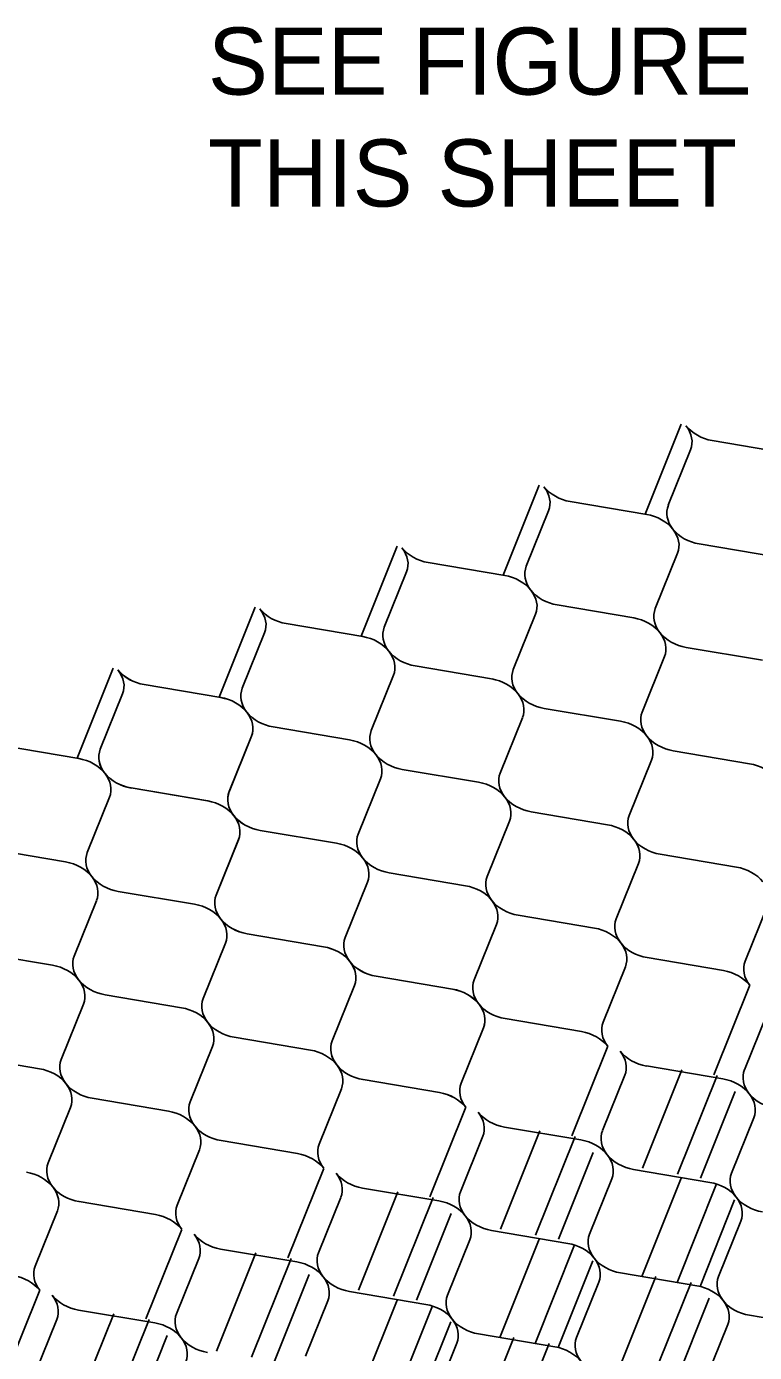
# Model space of a CAD drawing. Extents: x 638850 to 644908, y 297188 to 298900.
# Drawn here: x 639030.2 to 639062.7, y 298337.4 to 298396.7 of the extents above; entities that cross this region are included whole.
import ezdxf

# ---------------------------------------------------------------- set-up
doc = ezdxf.new("R2010")
doc.units = 0
doc.layers.add('1', color=7, linetype='Continuous')
doc.layers.add('2', color=7, linetype='Continuous')

msp = doc.modelspace()

# ---------------------------------------------------------------- linework, layer by layer
at = {"layer": '2'}
for p, q in [((639059.434, 298378.905), (639057.823, 298374.882)), ((639060.816, 298378.176), (639064.234, 298377.598)), ((639058.857, 298375.286), (639059.85, 298377.76)), ((639053.09, 298376.177), (639051.48, 298372.154)), ((639054.472, 298375.448), (639057.891, 298374.87)), ((639052.513, 298372.558), (639053.506, 298375.033)), ((639046.747, 298373.45), (639045.137, 298369.427)), ((639063.653, 298372.974), (639060.236, 298373.554)), ((639059.269, 298373.136), (639058.276, 298370.662)), ((639046.17, 298369.831), (639047.163, 298372.305)), ((639048.129, 298372.721), (639051.547, 298372.143)), ((639040.403, 298370.723), (639038.793, 298366.699)), ((639057.31, 298370.246), (639053.892, 298370.826)), ((639041.785, 298369.993), (639045.204, 298369.415)), ((639052.925, 298370.409), (639051.933, 298367.934)), ((639039.827, 298367.103), (639040.819, 298369.578)), ((639059.651, 298368.93), (639063.07, 298368.352)), ((639050.966, 298367.519), (639047.549, 298368.099)), ((639057.692, 298366.04), (639058.685, 298368.515)), ((639034.061, 298367.997), (639032.451, 298363.974)), ((639046.582, 298367.681), (639045.589, 298365.207)), ((639035.442, 298367.266), (639038.861, 298366.688)), ((639035.443, 298367.268), (639038.861, 298366.69)), ((639033.483, 298364.376), (639034.476, 298366.85)), ((639033.484, 298364.378), (639034.477, 298366.853)), ((639051.349, 298363.313), (639052.342, 298365.787)), ((639053.308, 298366.203), (639056.726, 298365.625)), ((639044.623, 298364.791), (639041.205, 298365.371)), ((639029.1, 298364.541), (639032.518, 298363.962)), ((639040.239, 298364.954), (639039.246, 298362.479)), ((639040.239, 298364.956), (639039.247, 298362.481)), ((639062.489, 298363.728), (639059.071, 298364.308)), ((639046.964, 298363.475), (639050.383, 298362.897)), ((639058.104, 298363.89), (639057.111, 298361.416)), ((639045.006, 298360.585), (639045.998, 298363.06)), ((639033.896, 298362.228), (639032.903, 298359.754)), ((639038.28, 298362.064), (639034.862, 298362.644)), ((639038.281, 298362.066), (639034.863, 298362.646)), ((639056.145, 298361), (639052.728, 298361.581)), ((639051.761, 298361.163), (639050.768, 298358.688)), ((639040.621, 298360.748), (639044.039, 298360.17)), ((639040.622, 298360.75), (639044.04, 298360.172)), ((639031.937, 298359.338), (639028.52, 298359.918)), ((639038.662, 298357.858), (639039.655, 298360.332)), ((639038.663, 298357.86), (639039.656, 298360.334)), ((639056.528, 298356.795), (639057.521, 298359.269)), ((639058.487, 298359.685), (639061.905, 298359.106)), ((639049.802, 298358.273), (639046.384, 298358.853)), ((639034.278, 298358.022), (639037.697, 298357.444)), ((639045.417, 298358.435), (639044.425, 298355.961)), ((639045.418, 298358.438), (639044.426, 298355.963)), ((639032.32, 298355.132), (639033.312, 298357.607)), ((639052.143, 298356.957), (639055.562, 298356.379)), ((639063.283, 298357.372), (639062.29, 298354.898)), ((639050.184, 298354.067), (639051.177, 298356.542)), ((639039.075, 298355.71), (639038.082, 298353.236)), ((639043.459, 298355.545), (639040.041, 298356.126)), ((639043.459, 298355.548), (639040.042, 298356.128)), ((639027.935, 298355.295), (639031.354, 298354.717)), ((639061.324, 298354.482), (639057.907, 298355.062)), ((639056.94, 298354.645), (639055.947, 298352.17)), ((639045.8, 298354.23), (639049.218, 298353.652)), ((639045.801, 298354.232), (639049.219, 298353.654)), ((639037.116, 298352.82), (639033.698, 298353.4)), ((639043.841, 298351.34), (639044.834, 298353.814)), ((639043.842, 298351.342), (639044.835, 298353.816)), ((639062.495, 298353.825), (639060.895, 298349.827)), ((639032.732, 298352.983), (639031.739, 298350.508)), ((639054.981, 298351.755), (639051.563, 298352.335)), ((639062.264, 298350.052), (639063.257, 298352.526)), ((639039.457, 298351.504), (639042.876, 298350.926)), ((639050.597, 298351.919), (639049.604, 298349.445)), ((639050.596, 298351.917), (639049.604, 298349.443)), ((639037.498, 298348.614), (639038.491, 298351.089)), ((639056.152, 298351.097), (639054.552, 298347.101)), ((639030.773, 298350.093), (639027.355, 298350.673)), ((639055.921, 298347.327), (639056.914, 298349.801)), ((639059.458, 298350.052), (639057.698, 298345.654)), ((639057.88, 298350.217), (639061.298, 298349.636)), ((639061.035, 298349.788), (639059.273, 298345.388)), ((639044.254, 298349.192), (639043.261, 298346.717)), ((639048.638, 298349.027), (639045.22, 298349.607)), ((639048.638, 298349.029), (639045.221, 298349.61)), ((639033.114, 298348.777), (639036.532, 298348.199)), ((639061.848, 298349.078), (639060.3, 298345.209)), ((639031.155, 298345.887), (639032.148, 298348.361)), ((639049.808, 298348.37), (639048.209, 298344.374)), ((639053.115, 298347.325), (639051.355, 298342.927)), ((639051.537, 298347.489), (639054.955, 298346.911)), ((639062.675, 298347.905), (639061.682, 298345.431)), ((639042.295, 298346.302), (639038.877, 298346.882)), ((639049.578, 298344.599), (639050.571, 298347.074)), ((639054.691, 298347.061), (639052.93, 298342.66)), ((639037.91, 298346.464), (639036.918, 298343.99)), ((639055.505, 298346.35), (639053.956, 298342.481)), ((639043.465, 298345.642), (639041.866, 298341.646)), ((639060.716, 298345.015), (639057.297, 298345.593)), ((639056.331, 298345.178), (639055.338, 298342.703)), ((639059.431, 298345.208), (639057.67, 298340.81)), ((639061.007, 298344.945), (639059.246, 298340.544)), ((639046.772, 298344.597), (639045.011, 298340.199)), ((639045.193, 298344.762), (639048.612, 298344.184)), ((639035.952, 298343.574), (639032.534, 298344.155)), ((639043.235, 298341.872), (639044.227, 298344.346)), ((639048.348, 298344.333), (639046.587, 298339.933)), ((639061.82, 298344.234), (639060.272, 298340.365)), ((639031.567, 298343.737), (639030.574, 298341.262)), ((639049.161, 298343.623), (639047.613, 298339.754)), ((639061.099, 298340.807), (639062.092, 298343.282)), ((639037.122, 298342.915), (639035.522, 298338.919)), ((639054.372, 298342.288), (639050.954, 298342.866)), ((639038.85, 298342.034), (639042.269, 298341.456)), ((639049.988, 298342.45), (639048.995, 298339.976)), ((639053.089, 298342.48), (639051.329, 298338.082)), ((639054.666, 298342.216), (639052.904, 298337.816)), ((639036.891, 298339.144), (639037.884, 298341.619)), ((639040.428, 298341.87), (639038.668, 298337.472)), ((639042.005, 298341.606), (639040.243, 298337.205)), ((639055.479, 298341.506), (639053.931, 298337.637)), ((639042.818, 298340.895), (639041.269, 298337.026)), ((639058.295, 298340.806), (639056.535, 298336.408)), ((639056.714, 298340.97), (639060.133, 298340.392)), ((639054.758, 298338.079), (639055.749, 298340.556)), ((639059.872, 298340.543), (639058.111, 298336.142)), ((639030.779, 298340.19), (639029.179, 298336.191)), ((639043.644, 298339.723), (639042.652, 298337.248)), ((639048.029, 298339.56), (639044.611, 298340.138)), ((639046.747, 298339.755), (639044.987, 298335.357)), ((639060.685, 298339.832), (639059.137, 298335.963)), ((639034.085, 298339.142), (639032.325, 298334.744)), ((639032.507, 298339.307), (639035.925, 298338.729)), ((639048.323, 298339.491), (639046.562, 298335.09)), ((639065.896, 298338.497), (639062.478, 298339.075)), ((639030.548, 298336.417), (639031.541, 298338.891)), ((639035.661, 298338.878), (639033.9, 298334.478)), ((639049.137, 298338.78), (639047.588, 298334.911)), ((639061.512, 298338.66), (639060.519, 298336.185)), ((639036.475, 298338.168), (639034.926, 298334.299)), ((639051.952, 298338.079), (639050.192, 298333.681)), ((639050.374, 298338.244), (639053.79, 298337.666)), ((639048.415, 298335.353), (639049.406, 298337.829)), ((639053.528, 298337.815), (639051.767, 298333.415))]:
    msp.add_line(p, q, dxfattribs=at)
for centre, start_param, end_param in [((639058.344, 298378.275), 3.045062, 3.936083), ((639060.946, 298379.394), 0.794491, 1.685512), ((639052.001, 298375.548), 3.045062, 3.936083), ((639054.603, 298376.666), 0.794491, 1.685512), ((639060.364, 298374.771), 6.186654, 7.077676), ((639057.762, 298373.652), 3.936083, 4.827105), ((639060.364, 298374.771), 0.794491, 1.685512), ((639057.762, 298373.652), 3.045062, 3.936083), ((639045.658, 298372.82), 3.045062, 3.936083), ((639048.259, 298373.939), 0.794491, 1.685512), ((639054.02, 298372.043), 6.186654, 7.077676), ((639051.419, 298370.925), 3.936083, 4.827105), ((639051.419, 298370.925), 3.045062, 3.936083), ((639054.02, 298372.043), 0.794491, 1.685512), ((639039.314, 298370.093), 3.045062, 3.936083), ((639041.916, 298371.211), 0.794491, 1.685512), ((639059.782, 298370.148), 6.186654, 7.077676), ((639057.18, 298369.029), 3.936083, 4.827105), ((639045.075, 298368.197), 3.936083, 4.827105), ((639047.677, 298369.316), 6.186654, 7.077676), ((639057.18, 298369.029), 3.045062, 3.936083), ((639059.782, 298370.148), 0.794491, 1.685512), ((639047.677, 298369.316), 0.794491, 1.685512), ((639045.075, 298368.197), 3.045062, 3.936083), ((639032.972, 298367.367), 3.045062, 3.936083), ((639035.573, 298368.486), 0.794491, 1.685512), ((639032.971, 298367.365), 3.045062, 3.936083), ((639035.572, 298368.484), 0.794491, 1.685512), ((639050.837, 298366.302), 3.936083, 4.827105), ((639053.438, 298367.421), 6.186654, 7.077676), ((639041.334, 298366.589), 6.186654, 7.077676), ((639038.732, 298365.47), 3.936083, 4.827105), ((639038.733, 298365.472), 3.936083, 4.827105), ((639050.837, 298366.302), 3.045062, 3.936083), ((639053.438, 298367.421), 0.794491, 1.685512), ((639038.732, 298365.47), 3.045062, 3.936083), ((639041.334, 298366.589), 0.794491, 1.685512), ((639038.733, 298365.472), 3.045062, 3.936083), ((639059.199, 298365.525), 6.186654, 7.077676), ((639047.095, 298364.693), 6.186654, 7.077676), ((639056.598, 298364.406), 3.936083, 4.827105), ((639044.493, 298363.574), 3.936083, 4.827105), ((639056.598, 298364.406), 3.045062, 3.936083), ((639059.199, 298365.525), 0.794491, 1.685512), ((639032.389, 298362.744), 3.936083, 4.827105), ((639034.99, 298363.861), 6.186654, 7.077676), ((639034.991, 298363.863), 6.186654, 7.077676), ((639044.493, 298363.574), 3.045062, 3.936083), ((639047.095, 298364.693), 0.794491, 1.685512), ((639062.359, 298362.511), 3.936083, 4.827105), ((639032.389, 298362.744), 3.045062, 3.936083), ((639034.991, 298363.863), 0.794491, 1.685512), ((639034.99, 298363.861), 0.794491, 1.685512), ((639050.254, 298361.679), 3.936083, 4.827105), ((639052.856, 298362.798), 6.186654, 7.077676), ((639040.751, 298361.966), 6.186654, 7.077676), ((639040.752, 298361.968), 6.186654, 7.077676), ((639052.856, 298362.798), 0.794491, 1.685512), ((639050.254, 298361.679), 3.045062, 3.936083), ((639038.15, 298360.847), 3.936083, 4.827105), ((639038.151, 298360.849), 3.936083, 4.827105), ((639038.151, 298360.849), 3.045062, 3.936083), ((639040.752, 298361.968), 0.794491, 1.685512), ((639038.15, 298360.847), 3.045062, 3.936083), ((639040.751, 298361.966), 0.794491, 1.685512), ((639056.015, 298359.784), 3.936083, 4.827105), ((639058.617, 298360.902), 6.186654, 7.077676), ((639046.513, 298360.07), 6.186654, 7.077676), ((639043.911, 298358.952), 3.936083, 4.827105), ((639043.912, 298358.954), 3.936083, 4.827105), ((639056.015, 298359.784), 3.045062, 3.936083), ((639058.617, 298360.902), 0.794491, 1.685512), ((639031.807, 298358.122), 3.936083, 4.827105), ((639034.409, 298359.24), 6.186654, 7.077676), ((639043.912, 298358.954), 3.045062, 3.936083), ((639043.911, 298358.952), 3.045062, 3.936083), ((639046.513, 298360.07), 0.794491, 1.685512), ((639031.807, 298358.122), 3.045062, 3.936083), ((639034.409, 298359.24), 0.794491, 1.685512), ((639052.274, 298358.175), 6.186654, 7.077676), ((639061.777, 298357.888), 3.936083, 4.827105), ((639049.672, 298357.056), 3.936083, 4.827105), ((639037.568, 298356.226), 3.936083, 4.827105), ((639040.169, 298357.343), 6.186654, 7.077676), ((639040.17, 298357.345), 6.186654, 7.077676), ((639049.672, 298357.056), 3.045062, 3.936083), ((639052.274, 298358.175), 0.794491, 1.685512), ((639040.169, 298357.343), 0.794491, 1.685512), ((639040.17, 298357.345), 0.794491, 1.685512), ((639037.568, 298356.226), 3.045062, 3.936083), ((639055.433, 298355.161), 3.936083, 4.827105), ((639058.035, 298356.28), 6.186654, 7.077676), ((639045.93, 298355.447), 6.186654, 7.077676), ((639045.931, 298355.449), 6.186654, 7.077676), ((639055.433, 298355.161), 3.045062, 3.936083), ((639058.035, 298356.28), 0.794491, 1.685512), ((639033.827, 298354.617), 6.186654, 7.077676), ((639043.329, 298354.329), 3.936083, 4.827105), ((639043.33, 298354.331), 3.936083, 4.827105), ((639031.225, 298353.499), 3.936083, 4.827105), ((639043.329, 298354.329), 3.045062, 3.936083), ((639045.93, 298355.447), 0.794491, 1.685512), ((639043.33, 298354.331), 3.045062, 3.936083), ((639045.931, 298355.449), 0.794491, 1.685512), ((639061.194, 298353.266), 3.936083, 4.827105), ((639063.796, 298354.384), 6.186654, 7.077676), ((639031.225, 298353.499), 3.045062, 3.936083), ((639033.827, 298354.617), 0.794491, 1.685512), ((639051.692, 298353.552), 6.186654, 7.077676), ((639049.09, 298352.433), 3.936083, 4.827105), ((639049.091, 298352.435), 3.936083, 4.827105), ((639036.986, 298351.603), 3.936083, 4.827105), ((639039.588, 298352.722), 6.186654, 7.077676), ((639049.091, 298352.435), 3.045062, 3.936083), ((639049.09, 298352.433), 3.045062, 3.936083), ((639051.692, 298353.552), 0.794491, 1.685512), ((639036.986, 298351.603), 3.045062, 3.936083), ((639039.588, 298352.722), 0.794491, 1.685512), ((639057.453, 298351.657), 6.186654, 7.077676), ((639054.851, 298350.538), 3.936083, 4.827105), ((639042.747, 298349.708), 3.936083, 4.827105), ((639045.349, 298350.827), 6.186654, 7.077676), ((639045.348, 298350.825), 6.186654, 7.077676), ((639055.408, 298350.315), 3.045062, 3.936083), ((639058.009, 298351.434), 0.794491, 1.685512), ((639033.244, 298349.995), 6.186654, 7.077676), ((639030.643, 298348.876), 3.936083, 4.827105), ((639045.348, 298350.825), 0.794491, 1.685512), ((639045.349, 298350.827), 0.794491, 1.685512), ((639042.747, 298349.708), 3.045062, 3.936083), ((639063.77, 298349.538), 6.186654, 7.077676), ((639030.643, 298348.876), 3.045062, 3.936083), ((639033.244, 298349.995), 0.794491, 1.685512), ((639051.109, 298348.929), 6.186654, 7.077676), ((639051.11, 298348.931), 6.186654, 7.077676), ((639061.169, 298348.42), 3.936083, 4.827105), ((639039.006, 298348.099), 6.186654, 7.077676), ((639048.508, 298347.811), 3.936083, 4.827105), ((639048.508, 298347.813), 3.936083, 4.827105), ((639061.169, 298348.42), 3.045062, 3.936083), ((639063.77, 298349.538), 0.794491, 1.685512), ((639036.404, 298346.98), 3.936083, 4.827105), ((639049.065, 298347.588), 3.045062, 3.936083), ((639051.666, 298348.706), 0.794491, 1.685512), ((639036.404, 298346.98), 3.045062, 3.936083), ((639039.006, 298348.099), 0.794491, 1.685512), ((639057.427, 298346.811), 6.186654, 7.077676), ((639054.826, 298345.692), 3.936083, 4.827105), ((639042.165, 298345.085), 3.936083, 4.827105), ((639044.767, 298346.204), 6.186654, 7.077676), ((639054.826, 298345.692), 3.045062, 3.936083), ((639057.427, 298346.811), 0.794491, 1.685512), ((639032.662, 298345.372), 6.186654, 7.077676), ((639030.06, 298344.253), 3.936083, 4.827105), ((639042.721, 298344.861), 3.045062, 3.936083), ((639045.323, 298345.979), 0.794491, 1.685512), ((639060.587, 298343.797), 3.936083, 4.827105), ((639063.188, 298344.915), 6.186654, 7.077676), ((639032.662, 298345.372), 0.794491, 1.685512), ((639030.06, 298344.253), 3.045062, 3.936083), ((639051.084, 298344.084), 6.186654, 7.077676), ((639060.587, 298343.797), 3.045062, 3.936083), ((639063.188, 298344.915), 0.794491, 1.685512), ((639038.423, 298343.476), 6.186654, 7.077676), ((639048.483, 298342.965), 3.936083, 4.827105), ((639035.822, 298342.358), 3.936083, 4.827105), ((639051.084, 298344.084), 0.794491, 1.685512), ((639048.483, 298342.965), 3.045062, 3.936083), ((639036.378, 298342.133), 3.045062, 3.936083), ((639038.98, 298343.252), 0.794491, 1.685512), ((639056.845, 298342.188), 6.186654, 7.077676), ((639054.244, 298341.07), 3.936083, 4.827105), ((639042.139, 298340.238), 3.936083, 4.827105), ((639044.741, 298341.356), 6.186654, 7.077676), ((639054.244, 298341.07), 3.045062, 3.936083), ((639056.845, 298342.188), 0.794491, 1.685512), ((639029.478, 298339.63), 3.936083, 4.827105), ((639032.08, 298340.749), 6.186654, 7.077676), ((639044.741, 298341.356), 0.794491, 1.685512), ((639042.139, 298340.238), 3.045062, 3.936083), ((639062.606, 298340.293), 6.186654, 7.077676), ((639060.005, 298339.174), 3.936083, 4.827105), ((639030.035, 298339.406), 3.045062, 3.936083), ((639032.637, 298340.525), 0.794491, 1.685512), ((639050.502, 298339.461), 6.186654, 7.077676), ((639060.005, 298339.174), 3.045062, 3.936083), ((639062.606, 298340.293), 0.794491, 1.685512), ((639038.398, 298338.629), 6.186654, 7.077676), ((639047.9, 298338.342), 3.936083, 4.827105), ((639035.796, 298337.511), 3.936083, 4.827105), ((639047.9, 298338.342), 3.045062, 3.936083), ((639050.502, 298339.461), 0.794491, 1.685512), ((639035.796, 298337.511), 3.045062, 3.936083), ((639038.398, 298338.629), 0.794491, 1.685512), ((639056.263, 298337.566), 6.186654, 7.077676), ((639053.661, 298336.447), 3.936083, 4.827105)]:
    msp.add_ellipse(centre, major_axis=(-1.543, 0.403), ratio=0.764477, start_param=start_param, end_param=end_param, dxfattribs=at)

# ---------------------------------------------------------------- texts
at = {"layer": '1'}
for s, p in [('SEE FIGURE A,', (639038.294, 298393.636)), ('THIS SHEET', (639038.294, 298388.636))]:
    msp.add_text(s, height=3, dxfattribs=at).set_placement(p)

doc.saveas('drawing.dxf')
